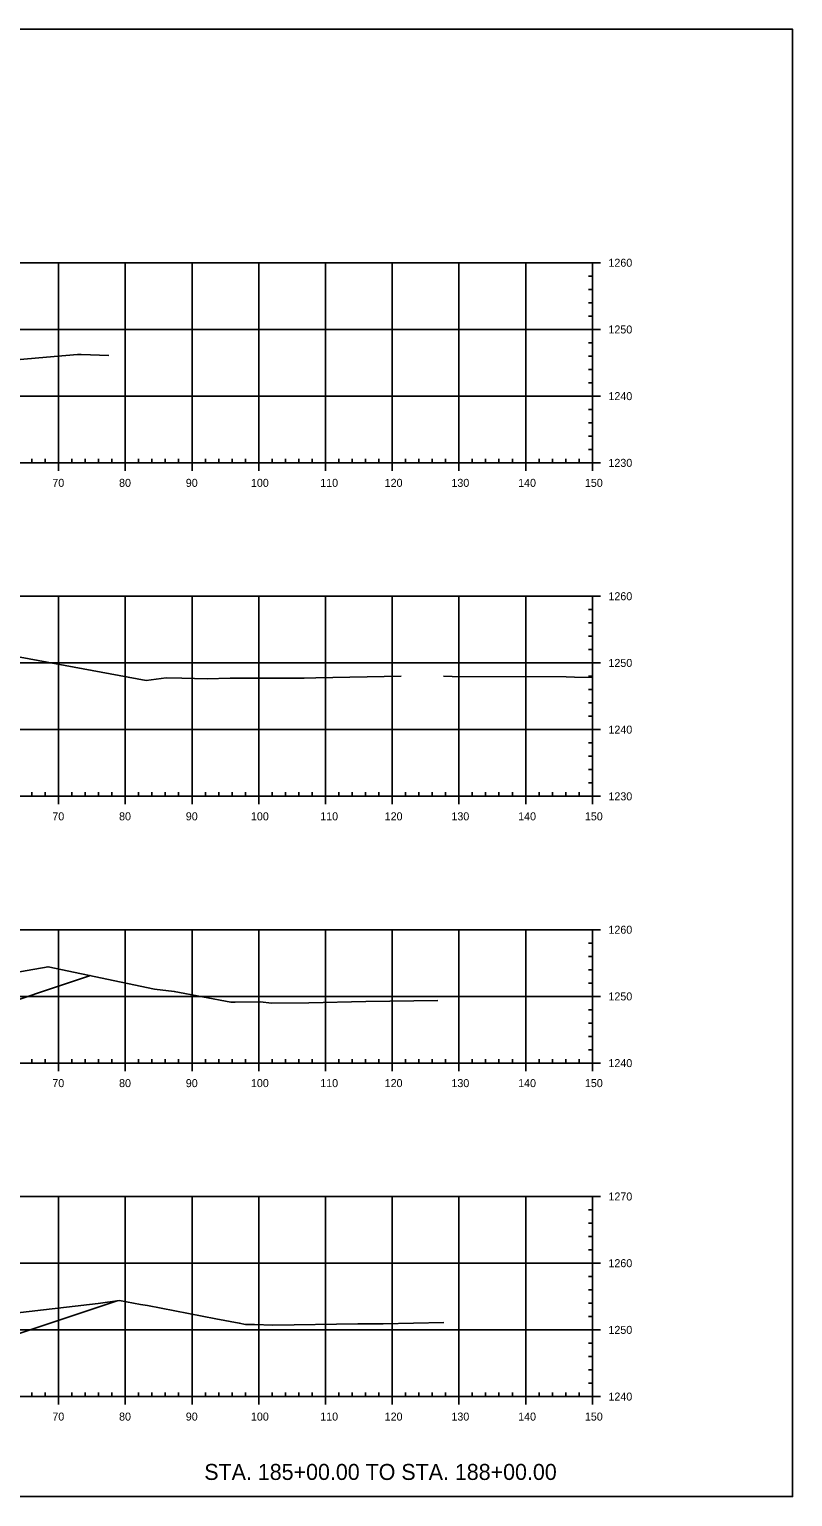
# Model space of a CAD drawing. Extents: x 659657 to 668193, y 633084 to 648639.
# Drawn here: x 667728.1 to 667842.5, y 643502.4 to 643722.4 of the extents above; entities that cross this region are included whole.
import ezdxf

# ---------------------------------------------------------------- set-up
doc = ezdxf.new("R2010")
doc.units = 0
for name, color, linetype in [('R_Axis', 7, 'Continuous'), ('R_Axis Annot', 7, 'Continuous'), ('R_Exist Surface', 7, 'Continuous'), ('R_Grid', 7, 'Continuous'), ('T_SIGNAL CONTROL CABINET', 7, 'Continuous'), ('TEMP_SIGNAL POLES', 7, 'Continuous'), ('TEMP_SIGNAL_HEAD_STAGE 5', 7, 'Continuous')]:
    doc.layers.add(name, color=color, linetype=linetype)

msp = doc.modelspace()

# ---------------------------------------------------------------- linework, layer by layer
at = {"layer": 'R_Axis'}
for p, q in [((667813.71, 643687.39), (667811.31, 643687.39)), ((667812.51, 643657.39), (667812.51, 643687.39)), ((667812.51, 643685.39), (667811.91, 643685.39)), ((667812.51, 643683.39), (667811.91, 643683.39)), ((667812.51, 643681.39), (667811.91, 643681.39)), ((667812.51, 643679.39), (667811.91, 643679.39)), ((667813.71, 643677.39), (667811.31, 643677.39)), ((667812.51, 643675.39), (667811.91, 643675.39)), ((667812.51, 643673.39), (667811.91, 643673.39)), ((667812.51, 643671.39), (667811.91, 643671.39)), ((667813.71, 643667.39), (667811.31, 643667.39)), ((667812.51, 643669.39), (667811.91, 643669.39)), ((667812.51, 643665.39), (667811.91, 643665.39)), ((667812.51, 643663.39), (667811.91, 643663.39)), ((667812.51, 643661.39), (667811.91, 643661.39)), ((667732.51, 643656.19), (667732.51, 643658.59)), ((667742.51, 643656.19), (667742.51, 643658.59)), ((667752.51, 643656.19), (667752.51, 643658.59)), ((667762.51, 643656.19), (667762.51, 643658.59)), ((667772.51, 643656.19), (667772.51, 643658.59)), ((667782.51, 643656.19), (667782.51, 643658.59)), ((667792.51, 643656.19), (667792.51, 643658.59)), ((667802.51, 643656.19), (667802.51, 643658.59)), ((667812.51, 643659.39), (667811.91, 643659.39)), ((667812.51, 643656.19), (667812.51, 643658.59)), ((667512.51, 643657.39), (667812.51, 643657.39)), ((667728.51, 643657.39), (667728.51, 643657.99)), ((667730.51, 643657.39), (667730.51, 643657.99)), ((667734.51, 643657.39), (667734.51, 643657.99)), ((667736.51, 643657.39), (667736.51, 643657.99)), ((667738.51, 643657.39), (667738.51, 643657.99)), ((667740.51, 643657.39), (667740.51, 643657.99)), ((667744.51, 643657.39), (667744.51, 643657.99)), ((667746.51, 643657.39), (667746.51, 643657.99)), ((667748.51, 643657.39), (667748.51, 643657.99)), ((667750.51, 643657.39), (667750.51, 643657.99)), ((667754.51, 643657.39), (667754.51, 643657.99)), ((667756.51, 643657.39), (667756.51, 643657.99)), ((667758.51, 643657.39), (667758.51, 643657.99)), ((667760.51, 643657.39), (667760.51, 643657.99)), ((667764.51, 643657.39), (667764.51, 643657.99)), ((667766.51, 643657.39), (667766.51, 643657.99)), ((667768.51, 643657.39), (667768.51, 643657.99)), ((667770.51, 643657.39), (667770.51, 643657.99)), ((667774.51, 643657.39), (667774.51, 643657.99)), ((667776.51, 643657.39), (667776.51, 643657.99)), ((667778.51, 643657.39), (667778.51, 643657.99)), ((667780.51, 643657.39), (667780.51, 643657.99)), ((667784.51, 643657.39), (667784.51, 643657.99)), ((667786.51, 643657.39), (667786.51, 643657.99)), ((667788.51, 643657.39), (667788.51, 643657.99)), ((667790.51, 643657.39), (667790.51, 643657.99)), ((667794.51, 643657.39), (667794.51, 643657.99)), ((667796.51, 643657.39), (667796.51, 643657.99)), ((667798.51, 643657.39), (667798.51, 643657.99)), ((667800.51, 643657.39), (667800.51, 643657.99)), ((667804.51, 643657.39), (667804.51, 643657.99)), ((667806.51, 643657.39), (667806.51, 643657.99)), ((667808.51, 643657.39), (667808.51, 643657.99)), ((667810.51, 643657.39), (667810.51, 643657.99)), ((667813.71, 643657.39), (667811.31, 643657.39)), ((667813.71, 643637.39), (667811.31, 643637.39)), ((667812.51, 643607.39), (667812.51, 643637.39)), ((667812.51, 643635.39), (667811.91, 643635.39)), ((667812.51, 643633.39), (667811.91, 643633.39)), ((667812.51, 643631.39), (667811.91, 643631.39)), ((667812.51, 643629.39), (667811.91, 643629.39)), ((667813.71, 643627.39), (667811.31, 643627.39)), ((667812.51, 643625.39), (667811.91, 643625.39)), ((667812.51, 643623.39), (667811.91, 643623.39)), ((667812.51, 643621.39), (667811.91, 643621.39)), ((667812.51, 643619.39), (667811.91, 643619.39)), ((667813.71, 643617.39), (667811.31, 643617.39)), ((667812.51, 643615.39), (667811.91, 643615.39)), ((667812.51, 643613.39), (667811.91, 643613.39)), ((667812.51, 643611.39), (667811.91, 643611.39)), ((667728.51, 643607.39), (667728.51, 643607.99)), ((667730.51, 643607.39), (667730.51, 643607.99)), ((667732.51, 643606.19), (667732.51, 643608.59)), ((667734.51, 643607.39), (667734.51, 643607.99)), ((667736.51, 643607.39), (667736.51, 643607.99)), ((667738.51, 643607.39), (667738.51, 643607.99)), ((667740.51, 643607.39), (667740.51, 643607.99)), ((667742.51, 643606.19), (667742.51, 643608.59)), ((667744.51, 643607.39), (667744.51, 643607.99)), ((667746.51, 643607.39), (667746.51, 643607.99)), ((667748.51, 643607.39), (667748.51, 643607.99)), ((667750.51, 643607.39), (667750.51, 643607.99)), ((667752.51, 643606.19), (667752.51, 643608.59)), ((667754.51, 643607.39), (667754.51, 643607.99)), ((667756.51, 643607.39), (667756.51, 643607.99)), ((667758.51, 643607.39), (667758.51, 643607.99)), ((667760.51, 643607.39), (667760.51, 643607.99)), ((667762.51, 643606.19), (667762.51, 643608.59)), ((667764.51, 643607.39), (667764.51, 643607.99)), ((667766.51, 643607.39), (667766.51, 643607.99)), ((667768.51, 643607.39), (667768.51, 643607.99)), ((667770.51, 643607.39), (667770.51, 643607.99)), ((667772.51, 643606.19), (667772.51, 643608.59)), ((667774.51, 643607.39), (667774.51, 643607.99)), ((667776.51, 643607.39), (667776.51, 643607.99)), ((667778.51, 643607.39), (667778.51, 643607.99)), ((667780.51, 643607.39), (667780.51, 643607.99)), ((667782.51, 643606.19), (667782.51, 643608.59)), ((667784.51, 643607.39), (667784.51, 643607.99)), ((667786.51, 643607.39), (667786.51, 643607.99)), ((667788.51, 643607.39), (667788.51, 643607.99)), ((667790.51, 643607.39), (667790.51, 643607.99)), ((667792.51, 643606.19), (667792.51, 643608.59)), ((667794.51, 643607.39), (667794.51, 643607.99)), ((667796.51, 643607.39), (667796.51, 643607.99)), ((667798.51, 643607.39), (667798.51, 643607.99)), ((667800.51, 643607.39), (667800.51, 643607.99)), ((667802.51, 643606.19), (667802.51, 643608.59)), ((667804.51, 643607.39), (667804.51, 643607.99)), ((667806.51, 643607.39), (667806.51, 643607.99)), ((667808.51, 643607.39), (667808.51, 643607.99)), ((667810.51, 643607.39), (667810.51, 643607.99)), ((667812.51, 643609.39), (667811.91, 643609.39)), ((667812.51, 643606.19), (667812.51, 643608.59)), ((667512.51, 643607.39), (667812.51, 643607.39)), ((667813.71, 643607.39), (667811.31, 643607.39)), ((667813.71, 643587.39), (667811.31, 643587.39)), ((667812.51, 643567.39), (667812.51, 643587.39)), ((667812.51, 643585.39), (667811.91, 643585.39)), ((667812.51, 643583.39), (667811.91, 643583.39)), ((667812.51, 643581.39), (667811.91, 643581.39)), ((667812.51, 643579.39), (667811.91, 643579.39)), ((667813.71, 643577.39), (667811.31, 643577.39)), ((667812.51, 643575.39), (667811.91, 643575.39)), ((667812.51, 643573.39), (667811.91, 643573.39)), ((667812.51, 643571.39), (667811.91, 643571.39)), ((667732.51, 643566.19), (667732.51, 643568.59)), ((667742.51, 643566.19), (667742.51, 643568.59)), ((667752.51, 643566.19), (667752.51, 643568.59)), ((667762.51, 643566.19), (667762.51, 643568.59)), ((667772.51, 643566.19), (667772.51, 643568.59)), ((667782.51, 643566.19), (667782.51, 643568.59)), ((667792.51, 643566.19), (667792.51, 643568.59)), ((667802.51, 643566.19), (667802.51, 643568.59)), ((667812.51, 643569.39), (667811.91, 643569.39)), ((667812.51, 643566.19), (667812.51, 643568.59)), ((667512.51, 643567.39), (667812.51, 643567.39)), ((667728.51, 643567.39), (667728.51, 643567.99)), ((667730.51, 643567.39), (667730.51, 643567.99)), ((667734.51, 643567.39), (667734.51, 643567.99)), ((667736.51, 643567.39), (667736.51, 643567.99)), ((667738.51, 643567.39), (667738.51, 643567.99)), ((667740.51, 643567.39), (667740.51, 643567.99)), ((667744.51, 643567.39), (667744.51, 643567.99)), ((667746.51, 643567.39), (667746.51, 643567.99)), ((667748.51, 643567.39), (667748.51, 643567.99)), ((667750.51, 643567.39), (667750.51, 643567.99)), ((667754.51, 643567.39), (667754.51, 643567.99)), ((667756.51, 643567.39), (667756.51, 643567.99)), ((667758.51, 643567.39), (667758.51, 643567.99)), ((667760.51, 643567.39), (667760.51, 643567.99)), ((667764.51, 643567.39), (667764.51, 643567.99)), ((667766.51, 643567.39), (667766.51, 643567.99)), ((667768.51, 643567.39), (667768.51, 643567.99)), ((667770.51, 643567.39), (667770.51, 643567.99)), ((667774.51, 643567.39), (667774.51, 643567.99)), ((667776.51, 643567.39), (667776.51, 643567.99)), ((667778.51, 643567.39), (667778.51, 643567.99)), ((667780.51, 643567.39), (667780.51, 643567.99)), ((667784.51, 643567.39), (667784.51, 643567.99)), ((667786.51, 643567.39), (667786.51, 643567.99)), ((667788.51, 643567.39), (667788.51, 643567.99)), ((667790.51, 643567.39), (667790.51, 643567.99)), ((667794.51, 643567.39), (667794.51, 643567.99)), ((667796.51, 643567.39), (667796.51, 643567.99)), ((667798.51, 643567.39), (667798.51, 643567.99)), ((667800.51, 643567.39), (667800.51, 643567.99)), ((667804.51, 643567.39), (667804.51, 643567.99)), ((667806.51, 643567.39), (667806.51, 643567.99)), ((667808.51, 643567.39), (667808.51, 643567.99)), ((667810.51, 643567.39), (667810.51, 643567.99)), ((667813.71, 643567.39), (667811.31, 643567.39)), ((667813.71, 643547.39), (667811.31, 643547.39)), ((667812.51, 643517.39), (667812.51, 643547.39)), ((667812.51, 643545.39), (667811.91, 643545.39)), ((667812.51, 643543.39), (667811.91, 643543.39)), ((667812.51, 643541.39), (667811.91, 643541.39)), ((667812.51, 643539.39), (667811.91, 643539.39)), ((667813.71, 643537.39), (667811.31, 643537.39)), ((667812.51, 643535.39), (667811.91, 643535.39)), ((667812.51, 643533.39), (667811.91, 643533.39)), ((667812.51, 643531.39), (667811.91, 643531.39)), ((667812.51, 643529.39), (667811.91, 643529.39)), ((667813.71, 643527.39), (667811.31, 643527.39)), ((667812.51, 643525.39), (667811.91, 643525.39)), ((667812.51, 643523.39), (667811.91, 643523.39)), ((667812.51, 643521.39), (667811.91, 643521.39)), ((667728.51, 643517.39), (667728.51, 643517.99)), ((667730.51, 643517.39), (667730.51, 643517.99)), ((667732.51, 643516.19), (667732.51, 643518.59)), ((667734.51, 643517.39), (667734.51, 643517.99)), ((667736.51, 643517.39), (667736.51, 643517.99)), ((667738.51, 643517.39), (667738.51, 643517.99)), ((667740.51, 643517.39), (667740.51, 643517.99)), ((667742.51, 643516.19), (667742.51, 643518.59)), ((667744.51, 643517.39), (667744.51, 643517.99)), ((667746.51, 643517.39), (667746.51, 643517.99)), ((667748.51, 643517.39), (667748.51, 643517.99)), ((667750.51, 643517.39), (667750.51, 643517.99)), ((667752.51, 643516.19), (667752.51, 643518.59)), ((667754.51, 643517.39), (667754.51, 643517.99)), ((667756.51, 643517.39), (667756.51, 643517.99)), ((667758.51, 643517.39), (667758.51, 643517.99)), ((667760.51, 643517.39), (667760.51, 643517.99)), ((667762.51, 643516.19), (667762.51, 643518.59)), ((667764.51, 643517.39), (667764.51, 643517.99)), ((667766.51, 643517.39), (667766.51, 643517.99)), ((667768.51, 643517.39), (667768.51, 643517.99)), ((667770.51, 643517.39), (667770.51, 643517.99)), ((667772.51, 643516.19), (667772.51, 643518.59)), ((667774.51, 643517.39), (667774.51, 643517.99)), ((667776.51, 643517.39), (667776.51, 643517.99)), ((667778.51, 643517.39), (667778.51, 643517.99)), ((667780.51, 643517.39), (667780.51, 643517.99)), ((667782.51, 643516.19), (667782.51, 643518.59)), ((667784.51, 643517.39), (667784.51, 643517.99)), ((667786.51, 643517.39), (667786.51, 643517.99)), ((667788.51, 643517.39), (667788.51, 643517.99)), ((667790.51, 643517.39), (667790.51, 643517.99)), ((667792.51, 643516.19), (667792.51, 643518.59)), ((667794.51, 643517.39), (667794.51, 643517.99)), ((667796.51, 643517.39), (667796.51, 643517.99)), ((667798.51, 643517.39), (667798.51, 643517.99)), ((667800.51, 643517.39), (667800.51, 643517.99)), ((667802.51, 643516.19), (667802.51, 643518.59)), ((667804.51, 643517.39), (667804.51, 643517.99)), ((667806.51, 643517.39), (667806.51, 643517.99)), ((667808.51, 643517.39), (667808.51, 643517.99)), ((667810.51, 643517.39), (667810.51, 643517.99)), ((667812.51, 643519.39), (667811.91, 643519.39)), ((667812.51, 643516.19), (667812.51, 643518.59)), ((667512.51, 643517.39), (667812.51, 643517.39)), ((667813.71, 643517.39), (667811.31, 643517.39))]:
    msp.add_line(p, q, dxfattribs=at)
at = {"layer": 'R_Exist Surface'}
for points in [[(667702.21, 643670.73), (667731.84, 643673.31), (667735.37, 643673.62), (667735.88, 643673.63), (667740.03, 643673.48)], [(667726.75, 643628.23), (667745.64, 643624.78), (667748.65, 643625.15), (667750.96, 643625.09), (667754.78, 643625.03), (667758.21, 643625.13), (667769.33, 643625.13), (667771.06, 643625.14), (667783.86, 643625.39)], [(667790.21, 643625.4), (667791.48, 643625.36), (667808.59, 643625.31), (667809.84, 643625.27), (667812.51, 643625.2)], [(667712.89, 643578.7), (667730.94, 643581.84), (667746.87, 643578.5), (667749.86, 643578.14), (667758.33, 643576.51), (667758.98, 643576.53), (667762.79, 643576.57), (667764.4, 643576.38), (667770.02, 643576.45), (667778.58, 643576.61), (667789.33, 643576.76)], [(667723.29, 643529.61), (667738.44, 643531.37), (667741.63, 643531.82), (667744.8, 643531.2), (667745.82, 643531.05), (667756.06, 643529.06), (667759.6, 643528.4), (667760.55, 643528.22), (667761.85, 643528.18), (667764.64, 643528.11), (667777.38, 643528.31), (667781.17, 643528.28), (667790.24, 643528.5)]]:
    msp.add_lwpolyline(points, dxfattribs=at)
at = {"layer": 'R_Grid'}
for p, q in [((667512.51, 643687.39), (667812.51, 643687.39)), ((667732.51, 643657.39), (667732.51, 643687.39)), ((667742.51, 643657.39), (667742.51, 643687.39)), ((667752.51, 643657.39), (667752.51, 643687.39)), ((667762.51, 643657.39), (667762.51, 643687.39)), ((667772.51, 643657.39), (667772.51, 643687.39)), ((667782.51, 643657.39), (667782.51, 643687.39)), ((667792.51, 643657.39), (667792.51, 643687.39)), ((667802.51, 643657.39), (667802.51, 643687.39)), ((667812.51, 643657.39), (667812.51, 643687.39)), ((667512.51, 643677.39), (667812.51, 643677.39)), ((667512.51, 643667.39), (667812.51, 643667.39)), ((667512.51, 643657.39), (667812.51, 643657.39)), ((667512.51, 643637.39), (667812.51, 643637.39)), ((667512.51, 643637.39), (667812.51, 643637.39)), ((667732.51, 643607.39), (667732.51, 643637.39)), ((667732.51, 643607.39), (667732.51, 643637.39)), ((667742.51, 643607.39), (667742.51, 643637.39)), ((667742.51, 643607.39), (667742.51, 643637.39)), ((667752.51, 643607.39), (667752.51, 643637.39)), ((667752.51, 643607.39), (667752.51, 643637.39)), ((667762.51, 643607.39), (667762.51, 643637.39)), ((667762.51, 643607.39), (667762.51, 643637.39)), ((667772.51, 643607.39), (667772.51, 643637.39)), ((667772.51, 643607.39), (667772.51, 643637.39)), ((667782.51, 643607.39), (667782.51, 643637.39)), ((667782.51, 643607.39), (667782.51, 643637.39)), ((667792.51, 643607.39), (667792.51, 643637.39)), ((667792.51, 643607.39), (667792.51, 643637.39)), ((667802.51, 643607.39), (667802.51, 643637.39)), ((667802.51, 643607.39), (667802.51, 643637.39)), ((667812.51, 643607.39), (667812.51, 643637.39)), ((667812.51, 643607.39), (667812.51, 643637.39)), ((667512.51, 643627.39), (667812.51, 643627.39)), ((667512.51, 643627.39), (667812.51, 643627.39)), ((667512.51, 643617.39), (667812.51, 643617.39)), ((667512.51, 643617.39), (667812.51, 643617.39)), ((667512.51, 643607.39), (667812.51, 643607.39)), ((667512.51, 643607.39), (667812.51, 643607.39)), ((667512.51, 643587.39), (667812.51, 643587.39)), ((667732.51, 643567.39), (667732.51, 643587.39)), ((667742.51, 643567.39), (667742.51, 643587.39)), ((667752.51, 643567.39), (667752.51, 643587.39)), ((667762.51, 643567.39), (667762.51, 643587.39)), ((667772.51, 643567.39), (667772.51, 643587.39)), ((667782.51, 643567.39), (667782.51, 643587.39)), ((667792.51, 643567.39), (667792.51, 643587.39)), ((667802.51, 643567.39), (667802.51, 643587.39)), ((667812.51, 643567.39), (667812.51, 643587.39)), ((667512.51, 643577.39), (667812.51, 643577.39)), ((667512.51, 643567.39), (667812.51, 643567.39)), ((667512.51, 643547.39), (667812.51, 643547.39)), ((667732.51, 643517.39), (667732.51, 643547.39)), ((667742.51, 643517.39), (667742.51, 643547.39)), ((667752.51, 643517.39), (667752.51, 643547.39)), ((667762.51, 643517.39), (667762.51, 643547.39)), ((667772.51, 643517.39), (667772.51, 643547.39)), ((667782.51, 643517.39), (667782.51, 643547.39)), ((667792.51, 643517.39), (667792.51, 643547.39)), ((667802.51, 643517.39), (667802.51, 643547.39)), ((667812.51, 643517.39), (667812.51, 643547.39)), ((667512.51, 643537.39), (667812.51, 643537.39)), ((667512.51, 643527.39), (667812.51, 643527.39)), ((667512.51, 643517.39), (667812.51, 643517.39))]:
    msp.add_line(p, q, dxfattribs=at)
at = {"layer": 'T_SIGNAL CONTROL CABINET'}
msp.add_lwpolyline([(667502.51, 643502.39), (667842.51, 643502.39), (667842.51, 643722.39), (667502.51, 643722.39)], close=True, dxfattribs=at)
at = {"layer": 'TEMP_SIGNAL_HEAD_STAGE 5'}
for points in [[(667673.01, 643575.41), (667696.99, 643571.39), (667703.5, 643569.21), (667737.3, 643580.51)], [(667673.01, 643526.48), (667696.99, 643522.48), (667705.21, 643519.73), (667741.31, 643531.77)]]:
    msp.add_lwpolyline(points, dxfattribs=at)

# ---------------------------------------------------------------- texts
at = {"layer": 'R_Axis Annot'}
for s, p in [('1260', (667814.91, 643686.79)), ('1250', (667814.91, 643676.79)), ('1240', (667814.91, 643666.79)), ('1230', (667814.91, 643656.79)), ('70', (667731.58, 643653.79)), ('80', (667741.58, 643653.79)), ('90', (667751.58, 643653.79)), ('100', (667761.34, 643653.79)), ('110', (667771.72, 643653.79)), ('120', (667781.38, 643653.79)), ('130', (667791.38, 643653.79)), ('140', (667801.38, 643653.79)), ('150', (667811.38, 643653.79)), ('1260', (667814.91, 643636.79)), ('1250', (667814.91, 643626.79)), ('1240', (667814.91, 643616.79)), ('1230', (667814.91, 643606.79)), ('70', (667731.58, 643603.79)), ('80', (667741.58, 643603.79)), ('90', (667751.58, 643603.79)), ('100', (667761.34, 643603.79)), ('110', (667771.72, 643603.79)), ('120', (667781.38, 643603.79)), ('130', (667791.38, 643603.79)), ('140', (667801.38, 643603.79)), ('150', (667811.38, 643603.79)), ('1260', (667814.91, 643586.79)), ('1250', (667814.91, 643576.79)), ('1240', (667814.91, 643566.79)), ('70', (667731.58, 643563.79)), ('80', (667741.58, 643563.79)), ('90', (667751.58, 643563.79)), ('100', (667761.34, 643563.79)), ('110', (667771.72, 643563.79)), ('120', (667781.38, 643563.79)), ('130', (667791.38, 643563.79)), ('140', (667801.38, 643563.79)), ('150', (667811.38, 643563.79)), ('1270', (667814.91, 643546.79)), ('1260', (667814.91, 643536.79)), ('1250', (667814.91, 643526.79)), ('1240', (667814.91, 643516.79)), ('70', (667731.58, 643513.79)), ('80', (667741.58, 643513.79)), ('90', (667751.58, 643513.79)), ('100', (667761.34, 643513.79)), ('110', (667771.72, 643513.79)), ('120', (667781.38, 643513.79)), ('130', (667791.38, 643513.79)), ('140', (667801.38, 643513.79)), ('150', (667811.38, 643513.79))]:
    msp.add_text(s, height=1.2, dxfattribs=at).set_placement(p)
at = {"layer": 'TEMP_SIGNAL POLES'}
msp.add_text('STA. 185+00.00 TO STA. 188+00.00', height=2.4, dxfattribs=at).set_placement((667754.35, 643504.89))

doc.saveas('drawing.dxf')
